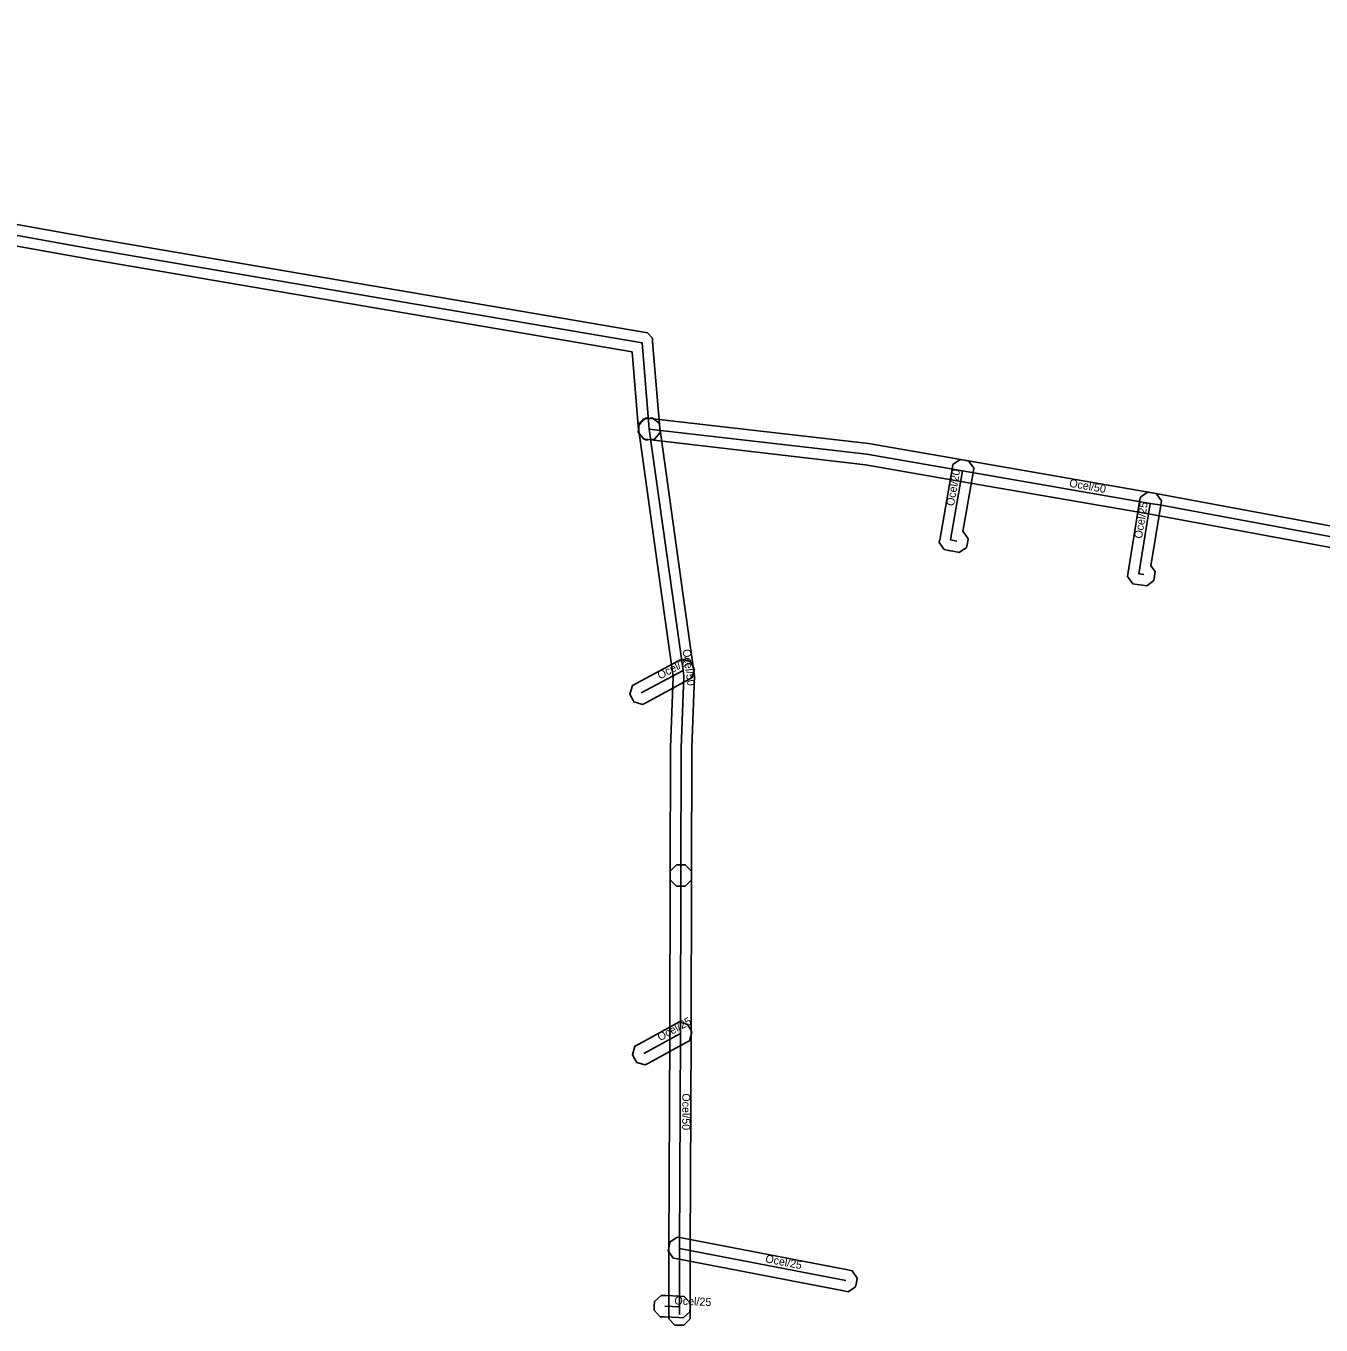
# Model space of a CAD drawing. Extents: x -569373 to -565022, y -1135090 to -1131496.
# Drawn here: x -565521.9 to -565400.5, y -1133375 to -1133253.2 of the extents above; entities that cross this region are included whole.
import ezdxf

# ---------------------------------------------------------------- set-up
doc = ezdxf.new("R2010")
doc.units = 0
for name, color, linetype in [('1', 7, 'Continuous'), ('24', 7, 'Continuous'), ('30', 7, 'Continuous')]:
    doc.layers.add(name, color=color, linetype=linetype)

msp = doc.modelspace()

# ---------------------------------------------------------------- linework, layer by layer
at = {"layer": '1'}
msp.add_lwpolyline([(-565551.395, -1133266.675), (-565515.457, -1133273.135), (-565464.022, -1133281.914), (-565463.685, -1133281.972), (-565463.222, -1133282.476), (-565463.194, -1133282.816), (-565462.514, -1133290.896), (-565462.479, -1133291.309), (-565463.013, -1133291.942), (-565463.426, -1133291.976), (-565463.839, -1133292.011), (-565464.472, -1133291.477), (-565464.506, -1133291.064), (-565465.122, -1133283.755), (-565515.803, -1133275.105), (-565551.745, -1133268.645)], dxfattribs=at)
for points in [[(-565462.577, -1133290.432), (-565462.52, -1133290.842), (-565460.36, -1133306.381), (-565459.359, -1133313.485), (-565459.278, -1133314.103), (-565459.53, -1133320.879), (-565459.55, -1133332.832), (-565459.551, -1133333.246), (-565460.138, -1133333.831), (-565460.552, -1133333.83), (-565460.966, -1133333.829), (-565461.551, -1133333.242), (-565461.55, -1133332.828), (-565461.53, -1133320.841), (-565461.282, -1133314.197), (-565461.341, -1133313.755), (-565462.34, -1133306.659), (-565464.5, -1133291.118), (-565464.557, -1133290.708), (-565464.058, -1133290.047), (-565463.648, -1133289.99), (-565463.238, -1133289.933)], [(-565463.806, -1133289.939), (-565463.395, -1133289.987), (-565442.967, -1133292.35), (-565433.969, -1133293.915), (-565416.389, -1133296.965), (-565415.523, -1133297.116), (-565385.408, -1133302.697), (-565385.001, -1133302.772), (-565384.532, -1133303.455), (-565384.607, -1133303.862), (-565384.682, -1133304.269), (-565385.365, -1133304.738), (-565385.772, -1133304.663), (-565415.877, -1133299.084), (-565416.731, -1133298.935), (-565434.311, -1133295.885), (-565443.253, -1133294.33), (-565463.625, -1133291.973), (-565464.036, -1133291.925), (-565464.551, -1133291.276), (-565464.503, -1133290.865), (-565464.455, -1133290.454)], [(-565433.155, -1133295.072), (-565434.115, -1133300.578), (-565434.09, -1133300.583), (-565433.621, -1133301.266), (-565433.697, -1133301.673), (-565433.773, -1133302.08), (-565434.456, -1133302.549), (-565434.863, -1133302.473), (-565435.453, -1133302.363), (-565435.857, -1133302.288), (-565436.326, -1133301.613), (-565436.255, -1133301.208), (-565435.125, -1133294.728), (-565435.054, -1133294.32), (-565434.376, -1133293.844), (-565433.968, -1133293.915), (-565433.56, -1133293.986), (-565433.084, -1133294.664)], [(-565415.573, -1133298.11), (-565416.497, -1133303.81), (-565416.092, -1133304.351), (-565416.15, -1133304.761), (-565416.208, -1133305.171), (-565416.871, -1133305.668), (-565417.281, -1133305.61), (-565417.771, -1133305.54), (-565418.187, -1133305.481), (-565418.436, -1133305.142), (-565418.684, -1133304.804), (-565418.617, -1133304.39), (-565417.547, -1133297.79), (-565417.481, -1133297.381), (-565416.809, -1133296.897), (-565416.4, -1133296.963), (-565415.991, -1133297.029), (-565415.507, -1133297.701)], [(-565459.512, -1133314.305), (-565459.877, -1133314.501), (-565463.787, -1133316.601), (-565464.152, -1133316.797), (-565464.945, -1133316.558), (-565465.141, -1133316.193), (-565465.337, -1133315.828), (-565465.098, -1133315.035), (-565464.733, -1133314.839), (-565460.823, -1133312.739), (-565460.458, -1133312.543), (-565459.665, -1133312.782), (-565459.469, -1133313.147), (-565459.273, -1133313.512)], [(-565459.549, -1133332.419), (-565459.55, -1133332.833), (-565459.6, -1133347.643), (-565459.62, -1133354.503), (-565459.67, -1133367.794), (-565459.69, -1133373.272), (-565459.69, -1133373.97), (-565459.69, -1133374.384), (-565460.276, -1133374.97), (-565460.69, -1133374.97), (-565461.104, -1133374.97), (-565461.69, -1133374.384), (-565461.69, -1133373.97), (-565461.69, -1133373.268), (-565461.67, -1133367.786), (-565461.62, -1133354.497), (-565461.6, -1133347.637), (-565461.55, -1133332.827), (-565461.549, -1133332.413), (-565460.961, -1133331.829), (-565460.547, -1133331.83), (-565460.133, -1133331.831)], [(-565459.756, -1133348.318), (-565460.119, -1133348.517), (-565463.529, -1133350.387), (-565463.892, -1133350.586), (-565464.688, -1133350.354), (-565464.887, -1133349.991), (-565465.086, -1133349.628), (-565464.854, -1133348.832), (-565464.491, -1133348.633), (-565461.081, -1133346.763), (-565460.718, -1133346.564), (-565459.922, -1133346.796), (-565459.723, -1133347.159), (-565459.524, -1133347.522)], [(-565460.888, -1133366.73), (-565460.481, -1133366.808), (-565444.891, -1133369.808), (-565444.484, -1133369.886), (-565444.02, -1133370.572), (-565444.098, -1133370.979), (-565444.176, -1133371.386), (-565444.862, -1133371.85), (-565445.269, -1133371.772), (-565460.859, -1133368.772), (-565461.266, -1133368.694), (-565461.73, -1133368.008), (-565461.652, -1133367.601), (-565461.574, -1133367.194)], [(-565462.41, -1133372.193), (-565461.996, -1133372.211), (-565460.646, -1133372.271), (-565460.232, -1133372.289), (-565459.673, -1133372.9), (-565459.691, -1133373.314), (-565459.709, -1133373.728), (-565460.32, -1133374.287), (-565460.734, -1133374.269), (-565462.084, -1133374.209), (-565462.498, -1133374.191), (-565463.057, -1133373.58), (-565463.039, -1133373.166), (-565463.021, -1133372.752)]]:
    msp.add_lwpolyline(points, close=True, dxfattribs=at)
at = {"layer": '24'}
for points in [[(-565623.24, -1133253.2), (-565620.94, -1133255.33), (-565620.56, -1133255.4), (-565599.83, -1133259.17), (-565551.57, -1133267.66), (-565515.63, -1133274.12), (-565464.19, -1133282.9), (-565463.51, -1133290.98)], [(-565463.51, -1133290.98), (-565443.11, -1133293.34), (-565434.14, -1133294.9), (-565416.56, -1133297.95), (-565415.7, -1133298.1), (-565385.59, -1133303.68)], [(-565463.51, -1133290.98), (-565461.35, -1133306.52), (-565460.35, -1133313.62), (-565460.28, -1133314.15), (-565460.53, -1133320.86), (-565460.55, -1133332.83)], [(-565434.68, -1133301.49), (-565435.27, -1133301.38), (-565434.14, -1133294.9)], [(-565417.14, -1133304.62), (-565417.63, -1133304.55), (-565416.56, -1133297.95)], [(-565460.35, -1133313.62), (-565464.26, -1133315.72)], [(-565460.55, -1133332.83), (-565460.6, -1133347.64), (-565460.62, -1133354.5), (-565460.67, -1133367.79), (-565460.69, -1133373.27), (-565460.69, -1133373.97)], [(-565460.6, -1133347.64), (-565464.01, -1133349.51)], [(-565460.67, -1133367.79), (-565445.08, -1133370.79)], [(-565462.04, -1133373.21), (-565460.69, -1133373.27)]]:
    msp.add_lwpolyline(points, dxfattribs=at)

# ---------------------------------------------------------------- texts
at = {"layer": '30'}
for s, rotation, p in [('Ocel/20', 80.10807, (-565434.957, -1133298.236)), ('Ocel/50', 350.15758, (-565424.187, -1133296.392)), ('Ocel/25', 80.79126, (-565417.335, -1133301.294)), ('Ocel/50', 278.01709, (-565460.397, -1133311.667)), ('Ocel/25', 28.23955, (-565462.505, -1133314.47)), ('Ocel/25', 28.7398, (-565462.505, -1133348.375)), ('Ocel/50', 269.83296, (-565460.417, -1133353.25)), ('Ocel/25', 349.10766, (-565452.675, -1133369.09)), ('Ocel/25', 357.4552, (-565461.165, -1133373.04))]:
    msp.add_text(s, height=0.75, rotation=rotation, dxfattribs=at).set_placement(p)

doc.saveas('drawing.dxf')
